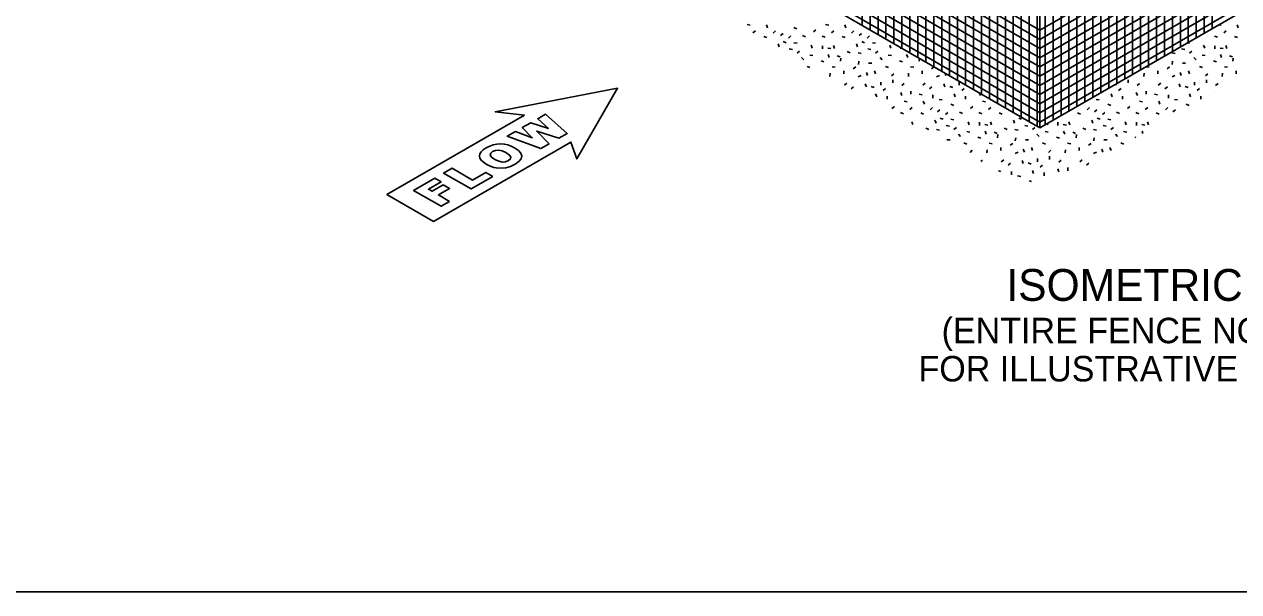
# Model space of a CAD drawing. Extents: x 99862 to 103151, y 100000 to 102076.
# Drawn here: x 101334 to 102097, y 100000 to 100356 of the extents above; entities that cross this region are included whole.
import ezdxf

# ---------------------------------------------------------------- set-up
doc = ezdxf.new("R2010")
doc.units = 0
for name, color, linetype in [('Level 1', 7, 'Continuous'), ('Level 20', 7, 'Continuous'), ('Level 3', 7, 'Continuous'), ('Level 5', 7, 'Continuous'), ('Level 9', 7, 'Continuous')]:
    doc.layers.add(name, color=color, linetype=linetype)

msp = doc.modelspace()

# ---------------------------------------------------------------- linework, layer by layer
at = {"layer": 'Level 1'}
msp.add_lwpolyline([(99862, 99999.5), (103151, 99999.5), (103151, 102075.5), (99862, 102075.5)], close=True, dxfattribs=at)
at = {"layer": 'Level 20'}
for points in [[(101648.14, 100298.92), (101561.73, 100249.03), (101591.03, 100232.12), (101677.44, 100282.01), (101681.1, 100271.44), (101706.74, 100315.84), (101629.83, 100301.04), (101648.14, 100298.92)], [(101663.77, 100280.88), (101658.53, 100277.86), (101637.44, 100285.59), (101642.52, 100288.53), (101653.12, 100284.64), (101646.86, 100291.04), (101652.22, 100294.13), (101663.32, 100290.52), (101656.57, 100296.64), (101661.46, 100299.46), (101675.08, 100287.41), (101669.82, 100284.38), (101655.93, 100288.89), (101663.77, 100280.88)], [(101633.61, 100265.55), (101630.49, 100265.77), (101628.9, 100266.09), (101627.32, 100266.57), (101625.77, 100267.21), (101624.24, 100268.01), (101622.39, 100269.25), (101621.06, 100270.52), (101620.26, 100271.83), (101620, 100273.18), (101620.26, 100274.52), (101621.05, 100275.83), (101622.36, 100277.1), (101624.2, 100278.34), (101626.38, 100279.42), (101628.6, 100280.21), (101630.86, 100280.67), (101633.17, 100280.83), (101635.47, 100280.68), (101637.71, 100280.24), (101639.9, 100279.48), (101642.01, 100278.43), (101644.52, 100276.68), (101645.97, 100274.96), (101646.46, 100273.24), (101646.05, 100271.51), (101644.69, 100269.8), (101642.32, 100268.12), (101639.41, 100266.71), (101636.55, 100265.86), (101633.61, 100265.55)], [(101634.34, 100269.44), (101636.37, 100269.61), (101638.17, 100270.31), (101639.43, 100271.36), (101639.73, 100272.52), (101638.86, 100273.84), (101636.61, 100275.42), (101634.22, 100276.51), (101632.01, 100276.93), (101629.98, 100276.75), (101628.17, 100276.03), (101626.99, 100275.01), (101626.71, 100273.85), (101627.51, 100272.53), (101629.55, 100271.07), (101632.07, 100269.89), (101634.34, 100269.44)], [(101601.11, 100244.71), (101595.8, 100241.64), (101578.56, 100251.6), (101591.83, 100259.26), (101595.81, 100256.96), (101587.85, 100252.37), (101590.17, 100251.03), (101597.13, 100255.05), (101601.11, 100252.75), (101594.15, 100248.73), (101601.11, 100244.71)], [(101628.26, 100260.38), (101614.66, 100252.53), (101597.41, 100262.49), (101602.72, 100265.55), (101615.66, 100258.08), (101623.95, 100262.87), (101628.26, 100260.38)]]:
    msp.add_lwpolyline(points, dxfattribs=at)
at = {"layer": 'Level 3'}
for p, q in [((101860.41, 100355.35), (101860.41, 100555.35)), ((101865.41, 100352.47), (101865.41, 100552.47)), ((101870.41, 100349.58), (101870.41, 100549.58)), ((101875.41, 100346.69), (101875.41, 100546.69)), ((101880.41, 100343.81), (101880.41, 100543.81)), ((101885.41, 100340.92), (101885.41, 100540.92)), ((101890.41, 100338.03), (101890.41, 100538.03)), ((101895.41, 100335.15), (101895.41, 100535.15)), ((101660.41, 100532.26), (101972.18, 100352.26)), ((101660.41, 100526.49), (101972.18, 100346.49)), ((101900.41, 100332.26), (101900.41, 100532.26)), ((101905.41, 100329.37), (101905.41, 100529.37)), ((101910.41, 100326.49), (101910.41, 100526.49)), ((101660.41, 100520.71), (101972.18, 100340.71)), ((101915.41, 100323.6), (101915.41, 100523.6)), ((101920.41, 100320.71), (101920.41, 100520.71)), ((101660.41, 100514.94), (101972.18, 100334.94)), ((101925.41, 100317.83), (101925.41, 100517.83)), ((101930.41, 100314.94), (101930.41, 100514.94)), ((101935.41, 100312.05), (101935.41, 100512.05)), ((101660.41, 100509.17), (101972.18, 100329.17)), ((101660.41, 100503.39), (101972.18, 100323.39)), ((101940.41, 100309.17), (101940.41, 100509.17)), ((101945.41, 100306.28), (101945.41, 100506.28)), ((101950.41, 100303.39), (101950.41, 100503.39)), ((101660.41, 100497.62), (101972.18, 100317.62)), ((101955.41, 100300.51), (101955.41, 100500.51)), ((101960.41, 100297.62), (101960.41, 100497.62)), ((101660.41, 100491.85), (101972.18, 100311.85)), ((101965.41, 100294.73), (101965.41, 100494.73)), ((101970.41, 100291.85), (101970.41, 100491.85)), ((101975.41, 100292.69), (101975.41, 100490.56)), ((101980.41, 100295.58), (101980.41, 100490.15)), ((101985.41, 100298.46), (101985.41, 100489.73)), ((101990.41, 100301.35), (101990.41, 100489.32)), ((101995.41, 100304.24), (101995.41, 100488.91)), ((102000.41, 100307.12), (102000.41, 100488.47)), ((101660.41, 100486.07), (101972.18, 100306.07)), ((102005.41, 100310.01), (102005.41, 100487.73)), ((102010.41, 100312.9), (102010.41, 100486.61)), ((102015.41, 100315.78), (102015.41, 100485.12)), ((102020.41, 100318.67), (102020.41, 100483.24)), ((102025.41, 100321.56), (102025.41, 100480.96)), ((101660.41, 100480.3), (101972.18, 100300.3)), ((101660.41, 100474.53), (101972.18, 100294.53)), ((102030.41, 100324.44), (102030.41, 100478.25)), ((102035.41, 100327.33), (102035.41, 100475)), ((101660.41, 100470.82), (101972.18, 100290.82)), ((102040.41, 100330.22), (102040.41, 100471.14)), ((102045.41, 100333.1), (102045.41, 100466.61)), ((102050.41, 100335.99), (102050.41, 100461.41)), ((102055.41, 100338.88), (102055.41, 100455.53)), ((102060.41, 100341.76), (102060.41, 100448.77)), ((102065.41, 100344.65), (102065.41, 100441.27)), ((102070.41, 100347.54), (102070.41, 100433.69)), ((102075.41, 100350.43), (102075.41, 100426.77)), ((102080.41, 100353.31), (102080.41, 100420.52)), ((101972.18, 100352.26), (102083.69, 100416.64)), ((101972.18, 100346.49), (102087.13, 100412.85)), ((101972.18, 100340.71), (102090.82, 100409.21)), ((101972.18, 100334.94), (102094.83, 100405.75)), ((101972.18, 100329.17), (102099.21, 100402.51)), ((101972.18, 100323.39), (102104.09, 100399.55)), ((101972.18, 100317.62), (102109.63, 100396.98)), ((101972.18, 100311.85), (102116.13, 100394.96)), ((101972.18, 100290.82), (102151.86, 100394.56)), ((101972.18, 100294.53), (102145.12, 100394.37)), ((101972.18, 100300.3), (102134.62, 100394.08)), ((101972.18, 100306.07), (102124.26, 100393.88))]:
    msp.add_line(p, q, dxfattribs=at)
at = {"layer": 'Level 5'}
for p, q in [((101788.12, 100355.74), (101790.09, 100355.38)), ((101791.8, 100350.55), (101793.32, 100351.85)), ((101800.89, 100353.81), (101800.22, 100355.69)), ((101804.48, 100350.41), (101805.95, 100351.77)), ((101817.54, 100353.87), (101819.4, 100353.13)), ((101829.86, 100351.15), (101831.38, 100352.45)), ((101837.44, 100355.74), (101839.41, 100355.38)), ((101841.12, 100350.55), (101842.64, 100351.85)), ((101850.21, 100353.81), (101849.54, 100355.69)), ((101853.8, 100350.41), (101855.26, 100351.77)), ((102084.47, 100355.65), (102085.99, 100355.38)), ((102087.7, 100350.55), (102089.22, 100351.85)), ((102096.79, 100353.81), (102096.11, 100355.69)), ((101798.58, 100348.34), (101800.44, 100347.6)), ((101808.23, 100341.84), (101807.56, 100343.72)), ((101809.19, 100348.94), (101810.71, 100350.24)), ((101810.84, 100345.12), (101812.7, 100344.38)), ((101814.19, 100347.33), (101815.7, 100348.63)), ((101817.54, 100344.37), (101819.51, 100344.01)), ((101822.97, 100348.84), (101824.83, 100348.1)), ((101835.23, 100348.54), (101837.09, 100347.8)), ((101847.89, 100348.34), (101849.75, 100347.6)), ((101857.54, 100341.84), (101856.87, 100343.72)), ((101858.51, 100348.94), (101860.02, 100350.24)), ((101860.16, 100345.12), (101862.01, 100344.38)), ((101863.5, 100347.33), (101865.02, 100348.63)), ((101866.86, 100344.37), (101868.82, 100344.01)), ((102064.74, 100344.26), (102066.09, 100344.01)), ((102071.39, 100348.1), (102071.4, 100348.1)), ((102081.81, 100348.54), (102083.67, 100347.8)), ((102094.47, 100348.34), (102096.33, 100347.6)), ((101814.63, 100340.45), (101816.59, 100340.09)), ((101819.51, 100337.88), (101821.03, 100339.18)), ((101827.49, 100336.63), (101829.46, 100336.27)), ((101829.1, 100340.93), (101828.43, 100342.82)), ((101835.52, 100342.54), (101835.52, 100340.54)), ((101838.85, 100341.05), (101840.82, 100340.7)), ((101839.76, 100335.1), (101839.08, 100336.98)), ((101843.07, 100340.83), (101842.4, 100342.72)), ((101844.78, 100336.17), (101846.64, 100335.43)), ((101851.11, 100338.78), (101852.97, 100338.04)), ((101857.84, 100337.94), (101859.81, 100337.58)), ((101863.94, 100340.45), (101865.91, 100340.09)), ((101868.83, 100337.88), (101870.35, 100339.18)), ((101876.81, 100336.63), (101878.77, 100336.27)), ((101878.42, 100340.93), (101877.75, 100342.82)), ((101884.84, 100341.25), (101884.84, 100340.54)), ((101889.07, 100335.1), (101888.4, 100336.98)), ((102055.1, 100337.94), (102057.07, 100337.58)), ((102061.2, 100340.45), (102063.17, 100340.09)), ((102066.09, 100337.88), (102067.61, 100339.18)), ((102074.07, 100336.63), (102076.04, 100336.27)), ((102075.68, 100340.93), (102075.01, 100342.82)), ((102082.1, 100342.54), (102082.1, 100340.54)), ((102085.42, 100341.05), (102087.39, 100340.7)), ((102086.33, 100335.1), (102085.66, 100336.98)), ((102089.65, 100340.83), (102088.98, 100342.72)), ((102091.36, 100336.17), (102093.21, 100335.43)), ((101823.69, 100333.63), (101822.34, 100335.1)), ((101825.78, 100329.53), (101827.64, 100328.79)), ((101834.57, 100333.08), (101836.45, 100332.41)), ((101841.56, 100329.29), (101843.53, 100328.93)), ((101847.08, 100334.75), (101846.89, 100332.76)), ((101856.39, 100329.17), (101854.76, 100328.02)), ((101858.29, 100332.75), (101858.05, 100330.76)), ((101864.43, 100331.47), (101866.43, 100331.47)), ((101873.01, 100333.63), (101871.66, 100335.1)), ((101875.1, 100329.53), (101876.96, 100328.79)), ((101883.88, 100333.08), (101885.76, 100332.41)), ((101890.88, 100329.29), (101892.84, 100328.93)), ((101896.38, 100334.59), (101896.2, 100332.76)), ((101905.71, 100329.17), (101904.07, 100328.02)), ((102038.82, 100329.29), (102040.79, 100328.93)), ((102053.66, 100329.17), (102052.02, 100328.02)), ((102055.56, 100332.75), (102055.31, 100330.76)), ((102061.69, 100331.47), (102063.69, 100331.47)), ((102070.27, 100333.63), (102068.92, 100335.1)), ((102072.36, 100329.53), (102074.22, 100328.79)), ((102081.14, 100333.08), (102083.03, 100332.41)), ((102088.14, 100329.29), (102090.11, 100328.93)), ((102093.66, 100334.75), (102093.47, 100332.76)), ((101840.35, 100325.19), (101840.15, 100323.2)), ((101848.89, 100326.75), (101848.89, 100324.75)), ((101857.91, 100322.94), (101859.75, 100323.71)), ((101863.74, 100323.73), (101863.07, 100325.62)), ((101868.87, 100324.84), (101868.2, 100326.72)), ((101878.89, 100323.55), (101880.36, 100324.91)), ((101879.61, 100321.11), (101879.61, 100319.11)), ((101889.66, 100325.19), (101889.47, 100323.2)), ((101898.2, 100326.75), (101898.2, 100324.75)), ((101907.22, 100322.94), (101909.07, 100323.71)), ((101913.06, 100323.73), (101912.51, 100325.28)), ((102027.56, 100321.11), (102027.56, 100319.11)), ((102037.61, 100325.19), (102037.42, 100323.2)), ((102046.15, 100326.75), (102046.15, 100324.75)), ((102055.17, 100322.94), (102057.02, 100323.71)), ((102061.01, 100323.73), (102060.33, 100325.62)), ((102066.13, 100324.84), (102065.46, 100326.72)), ((102076.15, 100323.55), (102077.62, 100324.91)), ((102076.87, 100321.11), (102076.87, 100319.11)), ((102086.93, 100325.19), (102086.73, 100323.2)), ((102095.46, 100326.75), (102095.46, 100324.75)), ((101849.26, 100317.66), (101850.78, 100318.96)), ((101853.48, 100315.45), (101855, 100316.75)), ((101863.07, 100316.59), (101862.4, 100318.48)), ((101866.15, 100316.96), (101868.01, 100316.22)), ((101872.07, 100319.71), (101872.07, 100317.71)), ((101873.65, 100314.34), (101875.17, 100315.64)), ((101885.45, 100311.26), (101884.78, 100313.15)), ((101885.31, 100317.46), (101886.83, 100318.76)), ((101890.97, 100313.97), (101890.97, 100311.97)), ((101898.58, 100317.66), (101900.09, 100318.96)), ((101902.8, 100315.45), (101904.32, 100316.75)), ((101912.39, 100316.59), (101911.72, 100318.48)), ((101915.47, 100316.96), (101917.33, 100316.22)), ((101921.39, 100319.71), (101921.39, 100317.71)), ((101922.97, 100314.34), (101924.48, 100315.64)), ((101934.77, 100311.26), (101934.25, 100312.73)), ((102020.02, 100318.44), (102020.02, 100317.71)), ((102021.6, 100314.34), (102023.12, 100315.64)), ((102033.4, 100311.26), (102032.73, 100313.15)), ((102033.26, 100317.46), (102034.77, 100318.76)), ((102038.91, 100313.97), (102038.91, 100311.97)), ((102046.52, 100317.66), (102048.04, 100318.96)), ((102050.74, 100315.45), (102052.26, 100316.75)), ((102060.33, 100316.59), (102059.66, 100318.48)), ((102063.42, 100316.96), (102065.27, 100316.22)), ((102069.33, 100319.71), (102069.33, 100317.71)), ((102070.91, 100314.34), (102072.43, 100315.64)), ((102082.09, 100313.02), (102082.04, 100313.15)), ((102082.57, 100317.46), (102084.09, 100318.76)), ((101869.57, 100310.36), (101868.9, 100312.24)), ((101876.09, 100310.86), (101876.09, 100308.86)), ((101886.76, 100307.66), (101888.72, 100307.31)), ((101896.2, 100311.99), (101898.17, 100311.63)), ((101899.52, 100305.73), (101898.85, 100307.62)), ((101904.94, 100311.56), (101904.94, 100309.56)), ((101908.77, 100308.77), (101910.73, 100308.41)), ((101916.17, 100305.8), (101918.03, 100305.05)), ((101918.89, 100310.36), (101918.22, 100312.24)), ((101925.41, 100310.86), (101925.41, 100308.86)), ((101936.07, 100307.66), (101938.04, 100307.31)), ((101998.15, 100305.73), (101998.13, 100305.8)), ((102007.4, 100308.77), (102009.36, 100308.41)), ((102014.8, 100305.8), (102016.66, 100305.05)), ((102017.52, 100310.36), (102016.85, 100312.24)), ((102024.04, 100310.86), (102024.04, 100308.86)), ((102034.7, 100307.66), (102036.67, 100307.31)), ((102044.15, 100311.99), (102046.12, 100311.63)), ((102047.47, 100305.73), (102046.8, 100307.62)), ((102052.88, 100311.56), (102052.88, 100309.56)), ((102056.71, 100308.77), (102058.68, 100308.41)), ((102064.12, 100305.8), (102065.98, 100305.05)), ((102066.84, 100310.36), (102066.16, 100312.24)), ((102073.35, 100310.86), (102073.35, 100308.86)), ((101879.18, 100303.08), (101880.7, 100304.38)), ((101884.55, 100300.47), (101886.4, 100299.72)), ((101890.44, 100302.48), (101891.95, 100303.78)), ((101897.21, 100300.27), (101899.07, 100299.52)), ((101903.11, 100302.33), (101904.58, 100303.7)), ((101907.82, 100300.87), (101909.34, 100302.17)), ((101912.82, 100299.26), (101914.33, 100300.56)), ((101921.6, 100300.77), (101923.46, 100300.02)), ((101928.49, 100303.08), (101930.01, 100304.38)), ((101933.86, 100300.47), (101935.72, 100299.72)), ((101939.75, 100302.48), (101941.27, 100303.78)), ((101946.53, 100300.27), (101948.38, 100299.52)), ((101995.84, 100300.27), (101997.7, 100299.52)), ((102001.74, 100302.33), (102003.21, 100303.7)), ((102006.45, 100300.87), (102007.97, 100302.17)), ((102011.45, 100299.26), (102012.97, 100300.56)), ((102020.23, 100300.77), (102022.09, 100300.02)), ((102027.13, 100303.08), (102028.64, 100304.38)), ((102032.49, 100300.47), (102034.35, 100299.72)), ((102038.38, 100302.48), (102039.9, 100303.78)), ((102045.16, 100300.27), (102047.01, 100299.52)), ((102051.06, 100302.33), (102052.53, 100303.7)), ((102055.77, 100300.87), (102057.29, 100302.17)), ((101892.26, 100293.11), (101891.72, 100294.64)), ((101900.43, 100290.71), (101902.28, 100289.97)), ((101906.86, 100293.76), (101906.19, 100295.65)), ((101907.16, 100289.86), (101909.13, 100289.51)), ((101909.47, 100297.05), (101911.33, 100296.3)), ((101913.26, 100292.38), (101915.22, 100292.02)), ((101916.17, 100296.3), (101918.14, 100295.94)), ((101918.14, 100289.8), (101919.66, 100291.11)), ((101927.73, 100292.86), (101927.06, 100294.74)), ((101934.15, 100294.46), (101934.15, 100292.46)), ((101937.48, 100292.98), (101939.45, 100292.62)), ((101941.7, 100292.76), (101941.03, 100294.64)), ((101949.74, 100290.71), (101951.6, 100289.97)), ((101956.18, 100293.76), (101955.5, 100295.65)), ((101956.47, 100289.86), (101958.44, 100289.51)), ((101958.79, 100297.05), (101960.64, 100296.3)), ((101962.57, 100292.38), (101964.54, 100292.02)), ((101967.46, 100289.8), (101968.98, 100291.11)), ((101977.05, 100292.86), (101976.82, 100293.5)), ((101983.47, 100294.46), (101983.47, 100292.46)), ((101986.79, 100292.98), (101988.76, 100292.62)), ((101991.02, 100292.76), (101990.35, 100294.64)), ((101999.06, 100290.71), (102000.91, 100289.97)), ((102005.49, 100293.76), (102004.82, 100295.65)), ((102005.79, 100289.86), (102007.76, 100289.51)), ((102008.1, 100297.05), (102009.96, 100296.3)), ((102011.89, 100292.38), (102013.86, 100292.02)), ((102014.8, 100296.3), (102016.77, 100295.94)), ((102016.77, 100289.8), (102018.29, 100291.11)), ((102026.36, 100292.86), (102025.69, 100294.74)), ((102032.78, 100294.46), (102032.78, 100292.46)), ((102036.11, 100292.98), (102038.08, 100292.62)), ((102040.33, 100292.76), (102039.66, 100294.64)), ((101913.75, 100283.4), (101915.75, 100283.4)), ((101922.32, 100285.55), (101920.97, 100287.03)), ((101926.12, 100288.56), (101928.09, 100288.2)), ((101933.2, 100285.01), (101935.08, 100284.33)), ((101938.39, 100287.03), (101937.71, 100288.91)), ((101943.41, 100288.1), (101945.27, 100287.35)), ((101945.71, 100286.67), (101945.52, 100284.68)), ((101956.92, 100284.67), (101956.68, 100282.69)), ((101963.06, 100283.4), (101965.06, 100283.4)), ((101971.64, 100285.55), (101970.29, 100287.03)), ((101975.44, 100288.56), (101977.4, 100288.2)), ((101982.51, 100285.01), (101984.4, 100284.33)), ((101987.7, 100287.03), (101987.03, 100288.91)), ((101992.73, 100288.1), (101994.58, 100287.35)), ((101995.03, 100286.67), (101994.83, 100284.68)), ((102006.24, 100284.67), (102005.99, 100282.69)), ((102012.38, 100283.4), (102014.38, 100283.4)), ((102020.95, 100285.55), (102019.6, 100287.03)), ((102024.75, 100288.56), (102026.72, 100288.2)), ((102031.83, 100285.01), (102032.44, 100284.79)), ((102036.91, 100287.33), (102036.35, 100288.91)), ((101924.41, 100281.46), (101926.27, 100280.71)), ((101928.21, 100275.48), (101929.67, 100276.84)), ((101938.98, 100277.12), (101938.79, 100275.13)), ((101940.19, 100281.21), (101942.16, 100280.85)), ((101947.52, 100278.67), (101947.52, 100276.67)), ((101955.03, 100281.1), (101953.39, 100279.95)), ((101956.54, 100274.87), (101958.39, 100275.64)), ((101962.38, 100275.66), (101961.7, 100277.54)), ((101967.5, 100276.77), (101966.83, 100278.65)), ((101973.73, 100281.46), (101975.59, 100280.71)), ((101977.52, 100275.48), (101978.99, 100276.84)), ((101988.29, 100277.12), (101988.1, 100275.13)), ((101989.51, 100281.21), (101991.48, 100280.85)), ((101996.83, 100278.67), (101996.83, 100276.67)), ((102004.34, 100281.1), (102002.7, 100279.95)), ((102005.85, 100274.87), (102007.7, 100275.64)), ((102011.69, 100275.66), (102011.02, 100277.54)), ((102016.82, 100276.77), (102016.14, 100278.65)), ((102023.05, 100281.46), (102024.9, 100280.71)), ((101935.1, 100269.79), (101936.14, 100270.69)), ((101947.89, 100269.59), (101949.41, 100270.89)), ((101952.11, 100267.38), (101953.63, 100268.68)), ((101961.7, 100268.52), (101961.03, 100270.4)), ((101964.79, 100268.89), (101966.64, 100268.14)), ((101970.7, 100271.63), (101970.7, 100269.63)), ((101972.28, 100266.27), (101973.8, 100267.57)), ((101978.24, 100273.04), (101978.24, 100271.04)), ((101983.94, 100269.39), (101985.46, 100270.69)), ((101997.21, 100269.59), (101998.73, 100270.89)), ((102001.43, 100267.38), (102002.95, 100268.68)), ((101946.08, 100263.81), (101947.49, 100263.56)), ((101954.25, 100263.49), (101954.25, 100261.49)), ((101958.08, 100260.7), (101960.05, 100260.34)), ((101968.2, 100262.29), (101967.53, 100264.17)), ((101974.72, 100262.78), (101974.72, 100260.78)), ((101984.08, 100263.19), (101983.41, 100265.07)), ((101989.6, 100265.9), (101989.6, 100263.9)), ((101965.49, 100257.72), (101966.92, 100257.15))]:
    msp.add_line(p, q, dxfattribs=at)
at = {"layer": 'Level 9'}
msp.add_line((101972.18, 100290.82), (101972.18, 100544.51), dxfattribs=at)

# ---------------------------------------------------------------- texts
at = {"layer": 'Level 20'}
for s, height, p in [('ISOMETRIC VIEW', 20, (101951.03, 100182.22)), ('(ENTIRE FENCE NOT SHOWN', 16, (101910.35, 100155.6)), ('FOR ILLUSTRATIVE PURPOSES)', 16, (101895.82, 100131.6))]:
    msp.add_text(s, height=height, dxfattribs=at).set_placement(p)

doc.saveas('drawing.dxf')
